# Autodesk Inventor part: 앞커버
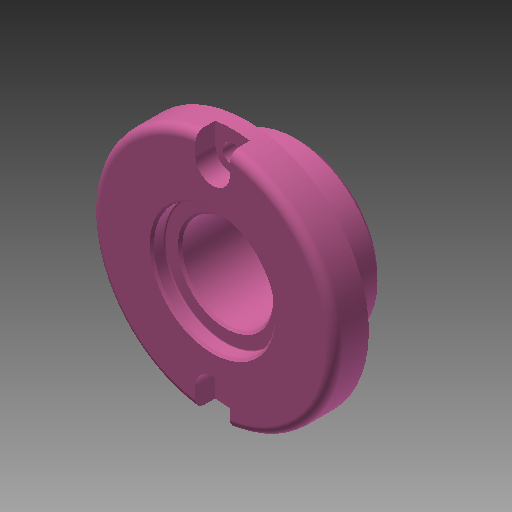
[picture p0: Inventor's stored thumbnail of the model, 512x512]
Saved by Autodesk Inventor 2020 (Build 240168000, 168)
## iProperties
Created: 2022-03
Part Number: 앞커버
Material: 일반
Document SubType Name: Modeling
Designer: mdu-01
Density: 1 g/cm^3
Appearance: 분홍색
Author: mdu-01
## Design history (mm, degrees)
sketch "스케치1"
  geometry: L1 (0, 0)-(0, -20); L2 (14, 0)-(28, 0); L3 (28, 0)-(28, -8); L4 (28, -8)-(19, -8); L5 (19, -8)-(19, -20); L6 (19, -20)-(10.5, -20); L7 (14, 0)-(14, -3); L8 (14, -3)-(10.5, -3); L9 (10.5, -3)-(10.5, -20)
  constraints: 18 end point, 5 perpendicular, 2 horizontal alignment, 2 parallel, 1 horizontal, 1 vertical
  dimensions: "d0" = 56 diameter of L3 L1; "d2" = 38 diameter of L5 L1; "d3" = 8 distance of L2.end L3.end; "d4" = 20 distance between parallel lines of L2 L6; "d5" = 21 diameter of L9 L1; "d6" = 28 diameter of L7 L1; "d7" = 3 distance of L2.start L7.end
revolve "회전1" sketch "스케치1" stored, may be unused: angle "d8" = 90 deg
fillet "모깎기1" dims "d9" = 0.5
chamfer "모따기1" distance "d10" = 0.5; stored, may be unused: second distance "d11" = 2, angle "d12" = 45 deg
chamfer "모따기2" distance "d13" = 1; stored, may be unused: second distance "d14" = 2, angle "d15" = 45 deg
fillet "모깎기2" dims "d32" = 2
sketch "스케치2" dims "d16" = 46
  geometry: 3 further points
  constraints: 2 vertical alignment, 1 coincident, 2 other
hole "구멍1" sketch "스케치2" at (0, 23) diameter "d18" = 4.5; stored, may be unused: countersink angle "d22" = 90 deg, drill point angle "d24" = 118 deg; dims "d19" = 6, "d20" = 8, "d21" = 4.6, "d23" = 8
sketch "스케치3"
  geometry: L1 (4, 23)-(4, 27.713); L2 (-4, 23)-(-4, 27.713); A1 r 4 centre (0, 23) between (-4, 23) and (4, 23) reference; A2 r 28 centre (0, 0) between (4, 27.713) and (-4, 27.713) reference; 1 further point
  constraints: 4 end point, 4 point on circle, 2 tangent, 1 parallel, 1 vertical
extrude "돌출1" cut sketch "스케치3" stored distance "d27" = 10; taper "d28" = 0 deg
fillet "모깎기3" dims "d33" = 0.3
node "솔리드1"
pattern_circular "원형 패턴1" dims angle "d30" = 360 deg
